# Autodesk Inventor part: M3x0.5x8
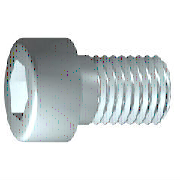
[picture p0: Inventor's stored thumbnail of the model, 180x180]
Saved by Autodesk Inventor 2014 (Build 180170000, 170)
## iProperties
IsCustomPart: 1
Company: 한국ATC센터
Created: 2009-02
Part Number: M3x0.5x8
Material: 강, 연강
Description: 6각머리 태핑 나사
Document SubType Name: Modeling
Standard: KS B 1003
Designer: KYOUNG IL JANG
Standards Organization: KS
Language: ko-KR
Size Designation: M 4 x 16
Categories: <MemberInstance><Categories><Category DisplayName="조임쇠" InternalName="e4da775c-781d-43d5-af7c-5136215cf5a6" Mnemonic="FSTN"><Category DisplayName="볼트" InternalN
Density: 7.86 g/cm^3
Mass: 2.43327 g
Surface Area: 3.56234 cm^2
Volume: 0.309576 cm^3
Vendor: CBT Solutions
Appearance: 강철
Author: KYOUNG IL JANG
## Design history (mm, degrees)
sketch "스케치1"
  geometry: L1 (-1, 0)-(16, 0); L2 (16, 0)-(16, 2); L3 (16, 2)-(1.75, 2); L4 (1.75, 2)-(1.32, 2); L5 (1.32, 2)-(0, 2); L6 (0, 2)-(0, 3.5); L7 (0, 3.5)-(-4, 3.5); L8 (-4, 3.5)-(-4, 1.732); L9 (-4, 1.732)-(-2, 1.732); L10 (-2, 1.732)-(-1, 0); L11 (-8, 0)-(20, 0) reference; L12 (0, -0.7)-(0, 4.2) reference; L13 (1.75, 2)-(0, 2)
  constraints: 22 end point, 6 parallel, 2 collinear, 2 perpendicular, 1 horizontal, 1 point on line
  dimensions: "d1" = 14.25 distance from line of L3.end L2 (= GEL); "d2" = 0.42952 distance of L4.end L3.end (computed from GAL); "d3" = 4 distance between parallel lines of L8 L6 (= KOH); "d4" = 2 distance of L8.end L9.end (= INTI); "d5" = 60 deg angle of L10 L1; "d6" = 4 diameter of L3 L1 (= GD); "d7" = 4 diameter of L5 L1 (= BDM); "d8" = 3.4641 diameter of L9 L1 (= 1.1547 x SW); "d9" = 7 diameter of L7 L1 (= KOD); "d26" = 16 distance between parallel lines of L12 L2 (= NLG)
revolve "본체" sketch "스케치1" stored, may be unused: angle "d10" = 90 deg
sketch "스케치2"
  geometry: L1 (0, -4.9)-(0, 4.9) reference; L2 (-4.9, 0)-(4.9, 0) reference; L3 (1.732, 0)-(0.866, -1.5); L4 (0.866, -1.5)-(-0.866, -1.5); L5 (-0.866, -1.5)-(-1.732, 0); L6 (-1.732, 0)-(-0.866, 1.5); L7 (-0.866, 1.5)-(0.866, 1.5); L8 (0.866, 1.5)-(1.732, 0); 2 further points
  constraints: 12 end point, 1 coincident, 1 horizontal alignment, 1 point on line, 12 other
extrude "슬롯" join sketch "스케치2" stored distance "d11" = 10; taper "d12" = 0 deg
workplane "Work Plane1"
fillet "Fillet2" dims "d30" = 0.1 (= R)
sketch "스케치4"
  geometry: C1 r 2.574 at (0, 0); 1 further point
  constraints: 1 centre point, 1 coincident
extrude "돌출3" cut sketch "스케치4" distance "d31" = 2; taper "d32" = 0 deg
chamfer "모따기3" distance "d33" = 0.4; stored, may be unused: second distance "d34" = 2, angle "d35" = 45 deg
body "Solid1"
fillet "모깎기1" dims "d17" = 0.4 (= RR)
feature "스레드" dims "d13" = 14.25 (= GEL), "d14" = 0
chamfer "모따기1" distance "d15" = 0.42941 (= -0.5 x SPD + 0.5 x GD); stored, may be unused: second distance "d16" = 0.42941 (= GUL), angle "d27" = 45 deg
other parameters: "GD" = 4 (= NND) [user parameter; used in 2 equation terms], "NLG" = 16 [user parameter; used in 1 equation term], "GEL" = 14.25 [user parameter; used in 2 equation terms], "KOD" = 7 [user parameter; used in 1 equation term], "KOH" = 4 [user parameter; used in 1 equation term], "INTI" = 2 [user parameter; used in 1 equation term], "GAL" = 0.42941 (= 0.61345 x PTC) [user parameter; used in 1 equation term], "GUL" = 0.42941 (= 0.61345 x PTC) [user parameter; used in 1 equation term], "BDM" = 4 (= NND) [user parameter; used in 1 equation term], "SW" = 3 [user parameter; used in 2 equation terms], "RR" = 0.4 [user parameter; used in 1 equation term], "SPD" = 3.14117 (= NND - 1.2269 x PTC) [user parameter; used in 1 equation term], "d19" = 0, "d28" = 0, "d29" = 0, "R" = 0.1 [user parameter; used in 1 equation term], "PHH" = 0.2 [user parameter], "GD1" = 3.14117 (= THREADDIA - 1.2269 x PTC) [user parameter], "THREADDIA" = 4 [user parameter; used in 1 equation term], "FAWI" = 45 deg [user parameter], "TPU" = 14.28571 (computed from PTC) [user parameter], "PTC" = 0.7 [user parameter; used in 5 equation terms], "NND" = 4 [user parameter; used in 3 equation terms], "TOA" = 30 deg [user parameter], "E0" = 3.465 (= 1.155 x SW) [user parameter]
